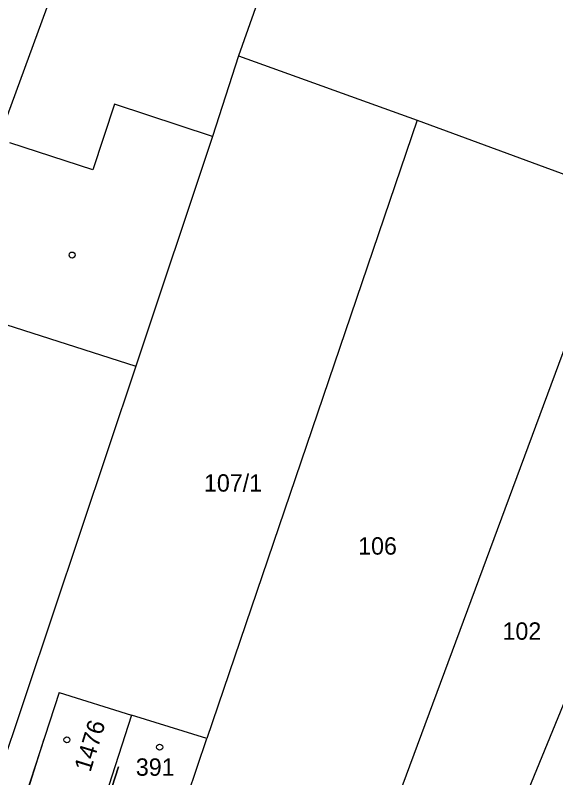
# Model space of a CAD drawing. Extents: x -643859 to -643594, y -1190913 to -1190609.
# Drawn here: x -643715.59 to -643684.48, y -1190761.05 to -1190717.16 of the extents above; entities that cross this region are included whole.
import ezdxf

# ---------------------------------------------------------------- set-up
doc = ezdxf.new("R2010")
doc.units = 0
for name, color, linetype in [('Budovy', 7, 'Continuous'), ('Hranice parcel', 7, 'Continuous'), ('Vrstva 1', 7, 'Continuous'), ('Vrstva 11', 7, 'Continuous'), ('Vrstva 38', 7, 'Continuous'), ('Vrstva 63', 7, 'Continuous')]:
    doc.layers.add(name, color=color, linetype=linetype)

msp = doc.modelspace()

# ---------------------------------------------------------------- linework, layer by layer
at = {"layer": 'Budovy'}
for points in [[(-643709.652, -1190760.428), (-643711.02, -1190764.64), (-643711.88, -1190764.35), (-643714.26, -1190763.55), (-643714.99, -1190763.31), (-643715.32, -1190763.19), (-643713.935, -1190758.809)], [(-643705.529, -1190761.609), (-643707.003, -1190766.017), (-643707.26, -1190765.93), (-643707.26, -1190765.93), (-643708.19, -1190765.6), (-643710.56, -1190764.8), (-643711.02, -1190764.64), (-643709.652, -1190760.428)]]:
    msp.add_lwpolyline(points, dxfattribs=at)
at = {"layer": 'Hranice parcel'}
for p, q in [((-643709.68, -1190705.55), (-643716.58, -1190724.3)), ((-643700.95, -1190714.38), (-643702.74, -1190719.49)), ((-643702.74, -1190719.49), (-643704.23, -1190724.13)), ((-643702.74, -1190719.49), (-643692.46, -1190723.19)), ((-643692.46, -1190723.19), (-643704.57, -1190758.79)), ((-643692.46, -1190723.19), (-643680.72, -1190727.52)), ((-643704.23, -1190724.13), (-643708.66, -1190737.36)), ((-643680.72, -1190727.52), (-643698.12, -1190774.45)), ((-643673.19, -1190730.3), (-643692.44, -1190777.33)), ((-643719.64, -1190733.83), (-643708.66, -1190737.36)), ((-643708.66, -1190737.36), (-643717.8, -1190764.65)), ((-643713.06, -1190756.15), (-643715.32, -1190763.06)), ((-643713.06, -1190756.15), (-643708.9, -1190757.45)), ((-643708.9, -1190757.45), (-643711.16, -1190764.47)), ((-643704.57, -1190758.79), (-643708.9, -1190757.45)), ((-643706.96, -1190765.89), (-643704.57, -1190758.79))]:
    msp.add_line(p, q, dxfattribs=at)
at = {"layer": 'Vrstva 1'}
for p, q in [((-643709.89, -1190722.28), (-643711.13, -1190726.06)), ((-643704.23, -1190724.13), (-643709.89, -1190722.28)), ((-643711.13, -1190726.06), (-643715.9, -1190724.5))]:
    msp.add_line(p, q, dxfattribs=at)
at = {"layer": 'Vrstva 11'}
for centre in [(-643712.624, -1190758.867), (-643707.282, -1190759.289)]:
    msp.add_circle(centre, 0.175, dxfattribs=at)
at = {"layer": 'Vrstva 38'}
msp.add_circle((-643712.32, -1190730.96), 0.175, dxfattribs=at)

# ---------------------------------------------------------------- texts
at = {"layer": 'Vrstva 63'}
for s, p in [('107/1', (-643704.73, -1190744.58)), ('106', (-643695.854, -1190748.206)), ('102', (-643687.543, -1190753.106)), ('391', (-643708.652, -1190760.936))]:
    msp.add_text(s, height=1, dxfattribs=at).set_placement(p)
msp.add_text('1476', height=1, rotation=72.8538, dxfattribs=at).set_placement((-643711.27, -1190760.767))

doc.saveas('drawing.dxf')
